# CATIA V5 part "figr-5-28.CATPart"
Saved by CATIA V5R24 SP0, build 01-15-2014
Part number: Part1
Bounding box of the stored display mesh (mm): x -100 to 100, y -100 to 100, z 0 to 57
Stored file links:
  D:\KAVITA\CATIA V5-6R2014 Project_ Kavita\CATIA V5-6R2014_partfiles\Partfiles\c05_catia_v5-6r2014_prt\figr-5-28.CATPart
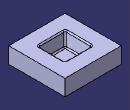
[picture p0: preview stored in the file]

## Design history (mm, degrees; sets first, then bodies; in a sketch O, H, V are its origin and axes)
Body1 (main body)
  Sketch1 on xy-plane, origin (0, 0, 0), H (1, 0, 0), V (0, 1, 0)
    line L1 (-100, 100) -> (100, 100)
    line L2 (100, 100) -> (100, -100)
    line L3 (100, -100) -> (-100, -100)
    line L4 (-100, -100) -> (-100, 100)
    axis line L5 (100, -100) -> (-100, 100)
    length L3 = 200
    length L2 = 200
    horizontal: L1 H, L3 H
    vertical: L2 V, L4 V
    midpoint: L5 O
  Pad1: profile Sketch1, direction (0, 0, 1), length 57
  Sketch2 on face of Pad1, origin (0, 0, 57), H (1, 0, 0), V (0, 1, 0)
    line L1 (-48.5141, 47.7936) -> (48.5141, 47.7936)
    line L2 (48.5141, 47.7936) -> (48.5141, -47.7936)
    line L3 (48.5141, -47.7936) -> (-48.5141, -47.7936)
    line L4 (-48.5141, -47.7936) -> (-48.5141, 47.7936)
    axis line L5 (48.5141, -47.7936) -> (-48.5141, 47.7936)
    horizontal: L1 H, L3 H
    vertical: L2 V, L4 V
    midpoint: O L5
  Pocket1: profile Sketch2, direction (0, 0, -1), length 42, opposite side up to face of Pad1
  Draft1: Angle 15, Neutral face of Pad1, PullDir face of Pocket1, SupportToDraft (face of Pocket1; face of Pocket1; face of Pocket1; face of Pocket1)
  Fillet1: radius 5, on edge [face of Pocket1 | face of Pocket1] (x4)
  Fillet2: radius 5, on edge [face of Pocket1 | face of Pocket1] (x4)
  Fillet3: radius 5, on edge [face of Pocket1 | face of Pad1]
